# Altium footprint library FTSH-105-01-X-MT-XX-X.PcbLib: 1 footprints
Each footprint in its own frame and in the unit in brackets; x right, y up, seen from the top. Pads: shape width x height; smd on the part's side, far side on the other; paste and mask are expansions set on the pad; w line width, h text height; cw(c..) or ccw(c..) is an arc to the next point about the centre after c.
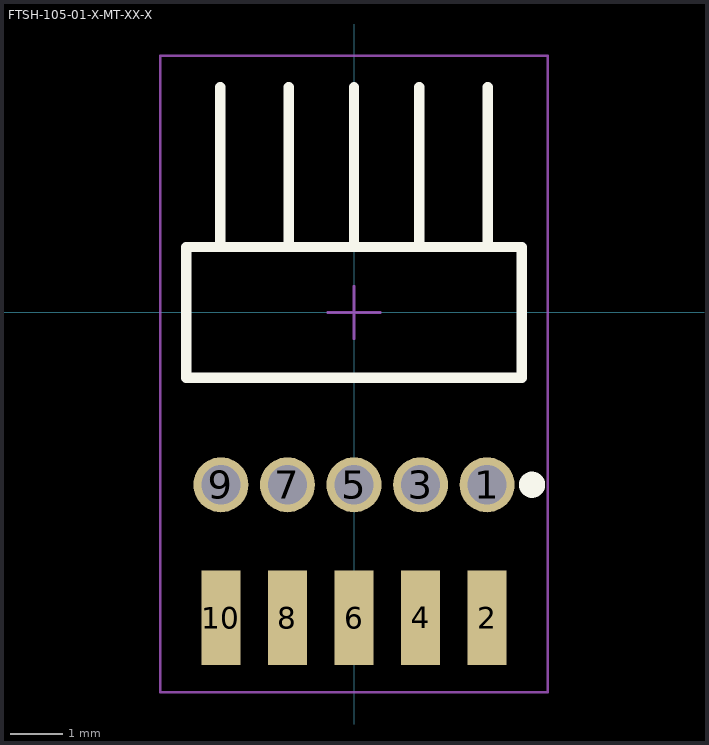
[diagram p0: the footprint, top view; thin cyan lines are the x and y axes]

## FTSH-105-01-X-MT-XX-X [mm] "1.27mm pitch, terminal strip; r/a, w/3.05mm length post, SMT, PTH"
height 5.97
pads (10):
  round 1.05 hole 0.75 mask+0: 1(2.54,-3.29) 3(1.27,-3.29) 5(0,-3.29) 7(-1.27,-3.29) 9(-2.54,-3.29)
  rect 0.75x1.8 smd mask+0: 2(2.54,-5.83) 6(0,-5.83) 8(-1.27,-5.83) 10(-2.54,-5.83)
  rect 0.75x1.8 smd paste+0 mask+0: 4(1.27,-5.83)
Top Overlay:
  circle w0.25: c3.4,-3.29 r0.125
  lines w0.2: -2.55,1.25 -2.55,4.3 ; -1.25,1.25 -1.25,4.3 ; 0,1.25 0,4.3 ; 1.25,1.25 1.25,4.3 ; 2.55,1.25 2.55,4.3 ; -3.2,-1.25 -3.2,1.25 3.2,1.25 3.2,-1.25 -3.2,-1.25
Mechanical 12:
  lines w0.001: -3.2,-1.25 -3.2,1.25 3.2,1.25 3.2,-1.25 -3.2,-1.25
Mechanical 13:
  lines w0.1: -2.55,1.255 -2.55,4.305 ; -1.25,1.255 -1.25,4.305 ; 0,1.255 0,4.305 ; 1.25,1.255 1.25,4.305 ; 2.55,1.255 2.55,4.305 ; -3.2,-1.25 -3.2,1.25 3.2,1.25 3.2,-1.25 -3.2,-1.25
  text ".Designator" at 0.254,0.254 h1.52
Mechanical 15:
  lines w0.05: -0.5,0 0.5,0 ; 0,-0.5 0,0.5 ; -3.7,-7.25 -3.7,4.9 3.7,4.9 3.7,-7.25 -3.7,-7.25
